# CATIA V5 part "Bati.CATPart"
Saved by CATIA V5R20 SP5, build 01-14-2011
Part number: Bati
Bounding box of the stored display mesh (mm): x -150 to 200, y -300 to 700, z -300 to 100
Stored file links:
  G:\IAO Final\Bati.CATPart
  G:\IAO Final\Assemblage Final.CATProduct
  G:\IAO Final\SKL Bati.CATPart
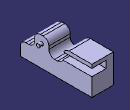
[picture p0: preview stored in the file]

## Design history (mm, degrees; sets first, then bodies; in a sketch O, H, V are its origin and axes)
Parameters
  `Rayon guidage roue` = 25 mm
  `Longueur guidage roue` = 50 mm
Set1
  Plane1: linked copy from another document
  Point1: linked copy from another document
Body1 (main body)
  Sketch1 on Plane1, origin (0, 0, 0), H (0, 1, 0), V (0, 0, 1)
    line L1 (-300, -300) -> (700, -300)
    line L2 (100, -100) -> (100, 100)
    line L3 (100, 100) -> (-100, 100)
    line L4 (-100, 100) -> (-100, -100)
    line L5 (-100, -100) -> (-300, -100)
    line L6 (-300, -100) -> (-300, -300)
    line L7 (100, -100) -> (300, -100)
    line L8 (700, -300) -> (700, 100)
    point P9 (700, 100)
    line L9 (700, 100) -> (300, 100)
    line L10 (300, 100) -> (300, -100)
    length L4 = 200
    length L6 = 200
    length L1 = 1000
    length L3 = 200
    length L7 = 200
    distance V L4 = 100
    length L5 = 200
    distance H L3 = 100
    horizontal: L1 H, L3 H, L5 H, L7 H, L9 H
    vertical: L2 V, L4 V, L6 V, L8 V, L10 V
    coincidence: P9 L3, L7 L5
  Pad1: profile Sketch1, direction (-1, 0, 0), length 150, mirrored extent
  Sketch2 on face of Pad1 from Sketch1.L8, origin (0, 700, 0), H (-1, 0, 0), V (0, 0, 1)
    line L1 (-150, 50) -> (50, 50)
    line L2 (50, 50) -> (50, -50)
    line L3 (50, -50) -> (-150, -50)
    line L4 (-150, -50) -> (-150, 50)
    length L2 = 100
    length L1 = 200
    distance V L2 = 50
    distance L3 H = 50
    horizontal: L1 H, L3 H
    vertical: L2 V, L4 V
  Pocket1: profile Sketch2, direction (0, -1, 0), through (limit type 6)
  Sketch3 on start face of Pad1, origin (150, 0, 0), H (0, 1, 0), V (0, 0, 1)
    circle A1 centre (0, 0) radius 25
    point P1 (0, 0)
    reference projected point E1 (0, 0) from Point1
    radius A1 = 25 {= `Rayon guidage roue`}
    coincidence: P1 E1
  Pad2: profile Sketch3, direction (1, 0, 0), length 50 {= `Longueur guidage roue`}
  Fillet1: radius 80, on edge [face of Pad1 from Sketch1.L7 | face of Pad1 from Sketch1.L2]; edge [face of Pad1 from Sketch1.L10 | face of Pad1 from Sketch1.L7]; edge [face of Pad1 from Sketch1.L4 | face of Pad1 from Sketch1.L5]; edge [face of Pad1 from Sketch1.L3 | face of Pad1 from Sketch1.L4]; edge [face of Pad1 from Sketch1.L2 | face of Pad1 from Sketch1.L3]; edge [face of Pad1 from Sketch1.L9 | face of Pad1 from Sketch1.L10]; edge [face of Pad1 from Sketch1.L5 | face of Pad1 from Sketch1.L6]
